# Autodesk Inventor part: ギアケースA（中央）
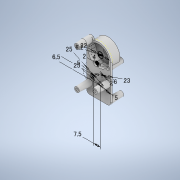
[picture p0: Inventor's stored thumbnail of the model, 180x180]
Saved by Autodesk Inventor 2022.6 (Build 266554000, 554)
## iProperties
Created: 2024-09
Part Number: ギアケースA（中央）
Material: 一般
Document SubType Name: Modeling
Designer: neo09
Density: 1 g/cm^3
Appearance: 既定
Author: neo09
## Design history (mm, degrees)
sketch "スケッチ1"
  geometry: 1 further point
sketch "スケッチ2"
  geometry: L1 (-7.211, 43)-(-7, 43); L2 (14, 31)-(14, -10); L3 (10.5, -13.5)-(-10.5, -13.5); L4 (-14, -10)-(-14, 43); L5 (-8.152, 45.596)-(-6, 43.649); A1 r 3.5 centre (-10.5, 43) between (-7, 43) and (-7.002, 43.123); A2 r 3.5 centre (-10.5, 43) between (-8.152, 45.596) and (-14, 43); A3 r 14 centre (0, 31) between (14, 31) and (-6, 43.649); A4 r 14 centre (0, 31) between (-7.002, 43.123) and (-7.211, 43); A5 r 3.5 centre (-10.5, -10) between (-14, -10) and (-10.5, -13.5); A6 r 3.5 centre (10.5, -10) between (10.5, -13.5) and (14, -10); 2 further points
  constraints: 12 point on circle, 10 end point, 7 tangent, 6 centre point, 2 parallel, 2 point on line, 1 horizontal, 1 perpendicular, 1 vertical alignment
  dimensions: "d1" = 13.5 distance from line of point (0, 0) L3; "d2" = 43 distance from line of L1 point (0, 0); "d4" = 31 distance of point (0, 0) A3.centre; "d6" = 6 horizontal distance of point (0, 43) L5.end; "d7" = 3.5 radius of A5 (derived); "d8" = 3.5 radius of A6 (derived)
extrude "押し出し1" new body sketch "スケッチ2" distance "d9" = 2; taper "d10" = 0 deg
sketch "スケッチ3"
  geometry: L1 (-14, 43)-(-14, -10) reference; L2 (14, -10)-(14, 31) reference; C1 r 3.5 at (-10.5, -1); C2 r 3.5 at (10.5, 8); 1 further point
  constraints: 2 centre point, 2 tangent
  dimensions: "d11" = 7 diameter of C1; "d12" = 1 vertical distance of C1.centre point (0, 0); "d13" = 7 diameter of C2; "d14" = 8 vertical distance of point (0, 0) C2.centre
extrude "押し出し2" join sketch "スケッチ3" distance "d15" = 15; taper "d16" = -2.29 deg
sketch "スケッチ4"
  geometry: C1 r 3.5 at (-10.5, 43); A1 r 3.5 centre (-10.5, 43) between (-8.152, 45.596) and (-14, 43) reference; 1 further point
  constraints: 2 concentric, 1 centre point
extrude "押し出し3" join sketch "スケッチ4" distance "d17" = 7; taper "d18" = 0 deg
sketch "スケッチ5"
  geometry: C1 r 3.5 at (0, 0); 1 further point
  constraints: 1 centre point
extrude "押し出し4" join sketch "スケッチ5" distance "d19" = 8; taper "d20" = -4.29 deg
sketch "スケッチ6"
  geometry: L1 (-14, -10)-(-14, 31) reference; L2 (14, 43)-(14, -10) reference; C1 r 3.5 at (-10.5, 24); C2 r 3.5 at (10.5, 32); C3 r 3.5 at (-10.5, -10); C4 r 3.5 at (10.5, -10); A1 r 3.5 centre (-10.5, -10) between (-14, -10) and (-10.5, -13.5) reference; A2 r 3.5 centre (10.5, -10) between (10.5, -13.5) and (14, -10) reference; 5 further points
  constraints: 4 centre point, 2 coincident, 2 tangent
  dimensions: "d21" = 7 diameter of C1; "d22" = 24 vertical distance of point (0, 0) C1.centre; "d23" = 7 diameter of C2; "d24" = 32 vertical distance of point (0, 0) C2.centre
extrude "押し出し5" join sketch "スケッチ6" distance "d25" = 14; taper "d26" = -2.45 deg
sketch "スケッチ7"
  geometry: C1 r 1.5 at (0, 0); 1 further point
  constraints: 1 centre point
  dimensions: "d27" = 3 diameter of C1
extrude "押し出し6" cut sketch "スケッチ7" distance "d28" = 8.5; taper "d29" = 0 deg
sketch "スケッチ8"
  geometry: C1 r 1.5 at (0, 0); 1 further point
  constraints: 1 centre point
  dimensions: "d30" = 3 diameter of C1
extrude "押し出し7" cut sketch "スケッチ8" distance "d31" = 8.5; taper "d32" = 0 deg
sketch "スケッチ9"
  geometry: C1 r 1.5 at (0, 0); 1 further point
  constraints: 1 centre point
  dimensions: "d33" = 3 diameter of C1
extrude "押し出し8" cut sketch "スケッチ9" distance "d34" = 8.5; taper "d35" = 0 deg
feature "ねじ1" dims "d36" = 8.5, "d37" = 0
feature "ねじ2" dims "d38" = 8.5, "d39" = 0
feature "ねじ3" dims "d40" = 8.5, "d41" = 0
sketch "スケッチ10"
  geometry: C1 r 1.5 at (0, 0); 1 further point
  constraints: 1 centre point
  dimensions: "d42" = 3 diameter of C1
extrude "押し出し9" cut sketch "スケッチ10" distance "d43" = 5; taper "d44" = 0 deg
sketch "スケッチ11"
  geometry: C1 r 1.5 at (0, 0); 1 further point
  constraints: 1 centre point
  dimensions: "d45" = 3 diameter of C1
extrude "押し出し10" cut sketch "スケッチ11" distance "d46" = 8.5; taper "d47" = 0 deg
sketch "スケッチ12"
  geometry: C1 r 1.5 at (0, 0); 1 further point
  constraints: 1 centre point
  dimensions: "d48" = 3 diameter of C1
extrude "押し出し11" cut sketch "スケッチ12" distance "d49" = 8.5; taper "d50" = 0 deg
sketch "スケッチ13"
  geometry: C1 r 1.5 at (0, 0); 1 further point
  constraints: 1 centre point
  dimensions: "d51" = 3 diameter of C1
extrude "押し出し12" cut sketch "スケッチ13" distance "d52" = 8.5; taper "d53" = 0 deg
feature "ねじ4" dims "d54" = 5, "d55" = 0
feature "ねじ5" dims "d56" = 8.5, "d57" = 0
feature "ねじ6" dims "d58" = 8.5, "d59" = 0
feature "ねじ7" dims "d60" = 8.5, "d61" = 0
sketch "スケッチ14"
  geometry: C1 r 14 at (0, 31); A1 r 14 centre (0, 31) between (14, 31) and (-6, 43.649) reference; 1 further point
  constraints: 2 concentric, 1 centre point
extrude "押し出し13" join sketch "スケッチ14" distance "d62" = 11; taper "d63" = 0 deg
sketch "スケッチ15"
  geometry: C1 r 12 at (0, 31); A1 r 14 centre (0, 31) between (14, 31) and (-6, 43.649) reference; 1 further point
  constraints: 1 centre point, 1 concentric
  dimensions: "d64" = 24 diameter of C1
extrude "押し出し14" cut sketch "スケッチ15" distance "d65" = 9; taper "d66" = 0 deg
sketch "スケッチ17" dims "d74" = 25, "d75" = 25
  geometry: C1 r 11.5 at (-3.764, 11.92); C2 r 11 at (0, 31); C3 r 3 at (-3.764, 11.92); 3 further points
  constraints: 3 centre point, 1 coincident, 1 concentric, 6 other
  dimensions: "d76" = 6.5 vertical distance of point (0, 0) point (7.5, 6.5); "d77" = 7.5 horizontal distance of point (0, 0) point (7.5, 6.5); "d78" = 23 diameter of C1; "d79" = 22 diameter of C2; "d80" = 6 diameter of C3
extrude "押し出し15" join sketch "スケッチ17" distance "d81" = 5.3; taper "d82" = -5.4 deg
sketch "スケッチ16" dims "d67" = 25, "d68" = 25, "d71" = 23, "d72" = 22
  geometry: C1 r 3 at (-3.764, 11.92); C2 r 2 at (3.723, 20.649); C3 r 2.5 at (0, 0); C4 r 2.5 at (7.5, 6.5); C5 r 1 at (-3.764, 11.92); C6 r 1 at (3.723, 20.649); C7 r 3.1 at (0, 31); A1 r 14 centre (0, 31) between (-9.769, 20.972) and (-13.014, 25.839) reference; 5 further points
  constraints: 7 centre point, 6 coincident, 14 other
  dimensions: "d69" = 6.5 vertical distance of point (0, 0) point (7.5, 6.5); "d70" = 7.5 horizontal distance of point (0, 0) point (7.5, 6.5); "d73" = 6 diameter of C1; "d87" = 4 diameter of C2; "d92" = 5 diameter of C3; "d93" = 5 diameter of C4; "d94" = 2 diameter of C5; "d95" = 2 diameter of C6; "d96" = 6.2 diameter of C7
sketch "スケッチ18"
  geometry: C1 r 2.5 at (-10.5, 32); C2 r 2.5 at (10.5, 24); C3 r 1.5 at (-10.5, 32) reference; A1 r 1.5 centre (10.5, 24) between (11.98, 23.756) and (11.295, 22.728) reference; 1 further point
  constraints: 2 centre point, 2 concentric
  dimensions: "d83" = 5 diameter of C1; "d84" = 5 diameter of C2
extrude "押し出し16" cut sketch "スケッチ18" distance "d85" = 9; taper "d86" = 0 deg
extrude "押し出し17" cut sketch "スケッチ16" distance "d88" = 7; taper "d90" = 0 deg; dims "d89" = 2, "d91" = 0
extrude "押し出し18" cut sketch "スケッチ16" extent not by distance; stored distance "d97" = 14; taper "d98" = 0 deg
node "ソリッド1"
other parameters: "d3" = 28, "d5" = 7
